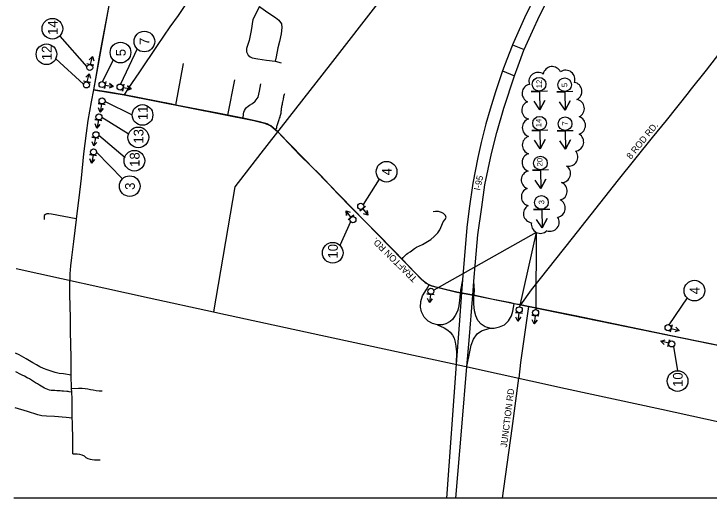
# Model space of a CAD drawing. Extents: x 1123038 to 1172987, y 554419 to 623636.
# Drawn here: x 1123076 to 1134979, y 566570 to 574867 of the extents above; entities that cross this region are included whole.
import ezdxf

# ---------------------------------------------------------------- set-up
doc = ezdxf.new("R2010")
doc.units = 0
for name, color, linetype in [('ANNOTATION', 7, 'Continuous'), ('CENTERLINE', 7, 'Continuous'), ('D_Text_Standard', 7, 'Continuous'), ('Default', 7, 'Continuous'), ('Maine_E911_Roads', 7, 'Continuous'), ('Metwp24L', 7, 'Continuous')]:
    doc.layers.add(name, color=color, linetype=linetype)

msp = doc.modelspace()

# ---------------------------------------------------------------- linework, layer by layer
at = {"layer": 'ANNOTATION'}
msp.add_line((1140976, 566570), (1123076, 566570), dxfattribs=at)
at = {"layer": 'CENTERLINE'}
for points in [[(1125179, 577813), (1125085, 577387), (1125042, 577195), (1124733, 575208), (1124438, 573567)], [(1124438, 573567), (1124965, 573483), (1124965, 573483), (1127185, 573041)], [(1127186, 573041), (1127367, 572996), (1127477, 572951), (1127593, 572849), (1129945, 570430), (1130047, 570325), (1130112, 570269)], [(1130112, 570269), (1130133, 570251), (1130186, 570222), (1130224, 570205), (1130658, 570099), (1130944, 570047), (1136685, 568871)]]:
    msp.add_lwpolyline(points, dxfattribs=at)
at = {"layer": 'D_Text_Standard'}
for p, q in [((1123860, 574488), (1124324, 573959)), ((1125184, 574269), (1124901, 573666)), ((1123794, 574095), (1124267, 573661)), ((1124776, 574080), (1124592, 573708)), ((1124637, 573369), (1125101, 573135)), ((1124582, 573095), (1125031, 572820)), ((1124532, 572789), (1124982, 572404)), ((1124490, 572496), (1124934, 572041)), ((1129331, 572038), (1129054, 571604)), ((1128841, 571307), (1128659, 570900)), ((1132020, 571124), (1130263, 570134)), ((1132020, 571124), (1131730, 569850)), ((1132020, 571124), (1132012, 569802)), ((1134603, 570000), (1134287, 569542)), ((1134369, 569169), (1134439, 568752))]:
    msp.add_line(p, q, dxfattribs=at)
for centre in [(1123735, 574613), (1125309, 574394), (1123633, 574176), (1124901, 574205), (1125278, 573135), (1125206, 572751), (1125138, 572352), (1129456, 572163), (1125059, 571916), (1128534, 570774), (1134728, 570125), (1134439, 568576)]:
    msp.add_circle(centre, 177, dxfattribs=at)
for centre, start, end in [((1132049, 573710), 54.2464, 199.2464), ((1132293, 573809), 24.6964, 169.6964), ((1132525, 573746), 340.1724, 125.1724), ((1131933, 573506), 101.6653, 246.6653), ((1132646, 573540), 295.741, 80.741), ((1132687, 573246), 294.9879, 79.9879), ((1131927, 573217), 110.9351, 255.9351), ((1131936, 572918), 107.5, 252.5), ((1132706, 572956), 287.5, 72.5), ((1132676, 572672), 275.5325, 60.5325), ((1131936, 572620), 107.5, 252.5), ((1131932, 572322), 105.7189, 250.7189), ((1132575, 572413), 256.7337, 41.7337), ((1132451, 572132), 270.7398, 55.7398), ((1131919, 572024), 104.404, 249.404), ((1132394, 571832), 282.7458, 67.7458), ((1131920, 571732), 110.9253, 255.9253), ((1132361, 571540), 279.2887, 64.2887), ((1131956, 571444), 118.2951, 263.2951), ((1132257, 571298), 249.2543, 34.2543), ((1132091, 571263), 170.2227, 315.2227)]:
    msp.add_arc(centre, 156, start, end, dxfattribs=at)
at = {"layer": 'Default'}
for points in [[(1124327, 574016), (1124446, 573988), (1124387, 574002), (1124419, 574138), (1124365, 574079), (1124419, 574138), (1124445, 574065)], [(1124270, 573718), (1124389, 573689), (1124330, 573704), (1124362, 573839), (1124308, 573781), (1124362, 573839), (1124388, 573767)], [(1124650, 573709), (1124629, 573588), (1124639, 573648), (1124777, 573625), (1124715, 573675), (1124777, 573625), (1124706, 573594)], [(1124958, 573666), (1124937, 573546), (1124948, 573606), (1125085, 573582), (1125023, 573633), (1125085, 573582), (1125014, 573552)], [(1132210, 573542), (1131935, 573538), (1132073, 573540), (1132078, 573226), (1132164, 573384), (1132078, 573226), (1131981, 573370)], [(1132648, 573535), (1132373, 573530), (1132510, 573533), (1132515, 573218), (1132601, 573377), (1132515, 573218), (1132419, 573362)], [(1124637, 573311), (1124516, 573333), (1124577, 573322), (1124552, 573185), (1124603, 573247), (1124552, 573185), (1124522, 573256)], [(1124582, 573037), (1124462, 573059), (1124522, 573048), (1124497, 572911), (1124548, 572972), (1124497, 572911), (1124467, 572982)], [(1132217, 572874), (1131942, 572869), (1132080, 572872), (1132085, 572557), (1132171, 572716), (1132085, 572557), (1131988, 572701)], [(1132654, 572866), (1132379, 572862), (1132517, 572864), (1132522, 572550), (1132608, 572708), (1132522, 572550), (1132425, 572694)], [(1124532, 572731), (1124411, 572753), (1124471, 572742), (1124446, 572605), (1124498, 572666), (1124446, 572605), (1124417, 572676)], [(1124490, 572438), (1124370, 572460), (1124430, 572449), (1124405, 572312), (1124456, 572374), (1124405, 572312), (1124375, 572383)], [(1132232, 572193), (1131957, 572188), (1132094, 572191), (1132099, 571876), (1132185, 572035), (1132099, 571876), (1132003, 572020)], [(1128799, 571346), (1128895, 571421), (1128847, 571383), (1128762, 571494), (1128773, 571415), (1128762, 571494), (1128834, 571468)], [(1129096, 571565), (1129000, 571491), (1129048, 571528), (1129133, 571417), (1129122, 571497), (1129133, 571417), (1129061, 571443)], [(1132250, 571518), (1131975, 571513), (1132113, 571516), (1132118, 571201), (1132204, 571360), (1132118, 571201), (1132021, 571345)], [(1130270, 570054), (1130148, 570068), (1130209, 570061), (1130192, 569922), (1130240, 569987), (1130192, 569922), (1130159, 569992)], [(1131783, 569736), (1131662, 569750), (1131723, 569743), (1131706, 569604), (1131753, 569669), (1131706, 569604), (1131672, 569673)], [(1132063, 569689), (1131942, 569704), (1132003, 569696), (1131986, 569558), (1132033, 569622), (1131986, 569558), (1131952, 569627)], [(1134344, 569537), (1134314, 569419), (1134329, 569478), (1134465, 569444), (1134407, 569499), (1134465, 569444), (1134392, 569419)], [(1134273, 569166), (1134303, 569284), (1134288, 569225), (1134152, 569259), (1134210, 569204), (1134152, 569259), (1134225, 569284)]]:
    msp.add_lwpolyline(points, dxfattribs=at)
for centre, radius in [((1124375, 573949), 51.9), ((1132069, 573662), 117), ((1132506, 573654), 117), ((1124318, 573651), 51.9), ((1124586, 573657), 51.9), ((1124894, 573614), 51.9), ((1124585, 573376), 51.9), ((1124531, 573102), 51.9), ((1132076, 572993), 117), ((1132513, 572986), 117), ((1124480, 572796), 51.9), ((1124439, 572503), 51.9), ((1132090, 572312), 117), ((1132109, 571637), 117), ((1129014, 571570), 51.9), ((1128881, 571341), 51.9), ((1130215, 570115), 51.9), ((1131728, 569797), 51.9), ((1132008, 569750), 51.9), ((1134277, 569491), 51.9), ((1134340, 569212), 51.9)]:
    msp.add_circle(centre, radius, dxfattribs=at)
at = {"layer": 'Maine_E911_Roads'}
for points in [[(1134361, 579160), (1133350, 577479), (1133077, 577028), (1132700, 576397), (1132542, 576128), (1132469, 576007), (1132208, 575573), (1132008, 575192), (1131818, 574801), (1131614, 574338)], [(1131810, 574255), (1131981, 574632), (1132046, 574774), (1132130, 574949), (1132308, 575290), (1132437, 575529), (1132637, 575882), (1132759, 576087), (1132857, 576253), (1133391, 577168), (1133611, 577543), (1134066, 578317), (1134254, 578635), (1134576, 579178)], [(1124822, 575809), (1124740, 575234), (1124668, 574827), (1124576, 574348), (1124517, 574035), (1124471, 573763), (1124438, 573567)], [(1126236, 575360), (1126156, 575239), (1126058, 575098), (1125890, 574841), (1125746, 574645), (1125527, 574323), (1125226, 573875), (1125024, 573582), (1124965, 573483)], [(1127283, 574992), (1127165, 574774), (1127137, 574585), (1127102, 574413), (1127059, 574276), (1127060, 574217), (1127087, 574162), (1127122, 574131), (1127157, 574112), (1127255, 574097), (1127398, 574075), (1127550, 574060)], [(1127283, 574992), (1127305, 574978), (1127384, 574919), (1127477, 574858), (1127554, 574807), (1127609, 574762), (1127660, 574698), (1127666, 574633), (1127649, 574526), (1127623, 574392), (1127597, 574287), (1127568, 574134), (1127550, 574060)], [(1135452, 574583), (1135423, 574548), (1135180, 574229), (1134927, 573903), (1134650, 573556), (1134620, 573517), (1134244, 573043), (1134002, 572749), (1133422, 572023), (1132636, 571025), (1131932, 570140), (1131751, 569881)], [(1131614, 574338), (1131607, 574322), (1131515, 574087), (1131444, 573891)], [(1131614, 574338), (1131810, 574255)], [(1131649, 573805), (1131707, 573975), (1131806, 574245), (1131810, 574255)], [(1125851, 573304), (1125978, 574020)], [(1127550, 574060), (1127654, 574030)], [(1131444, 573891), (1131414, 573805), (1131320, 573531), (1131230, 573237), (1131159, 572983), (1131076, 572665), (1131021, 572408), (1130933, 571968), (1130870, 571531), (1130831, 571207), (1130756, 570311)], [(1131444, 573891), (1131649, 573805)], [(1130953, 570288), (1130980, 570617), (1131019, 571083), (1131086, 571557), (1131139, 571936), (1131255, 572474), (1131342, 572835), (1131463, 573254), (1131649, 573805)], [(1126741, 573130), (1126861, 573738)], [(1127000, 573079), (1127009, 573154), (1127015, 573185), (1127026, 573214), (1127041, 573241), (1127061, 573264), (1127085, 573285), (1127111, 573301), (1127161, 573332), (1127204, 573371), (1127241, 573416), (1127258, 573443), (1127279, 573543), (1127304, 573667)], [(1124438, 573567), (1124400, 573358), (1124343, 573039), (1124311, 572822), (1124269, 572468), (1124227, 572052), (1124185, 571715), (1124140, 571358)], [(1124965, 573483), (1124698, 573526), (1124438, 573567)], [(1125851, 573304), (1125778, 573318), (1124965, 573483)], [(1127555, 572883), (1127566, 572896), (1127572, 572903), (1127576, 572916), (1127577, 572929), (1127580, 572943), (1127583, 572957), (1127588, 572972), (1127592, 572987), (1127599, 573005), (1127605, 573023), (1127611, 573042), (1127619, 573060), (1127625, 573080), (1127632, 573098), (1127636, 573116), (1127642, 573134), (1127647, 573150), (1127650, 573167), (1127651, 573185), (1127654, 573201), (1127656, 573218), (1127657, 573234), (1127660, 573251), (1127663, 573267), (1127666, 573284), (1127669, 573303), (1127674, 573323), (1127677, 573343), (1127681, 573363), (1127684, 573383), (1127689, 573404), (1127692, 573424), (1127695, 573442), (1127699, 573458), (1127702, 573475), (1127707, 573491), (1127713, 573504)], [(1126741, 573130), (1126593, 573159), (1125851, 573304)], [(1127000, 573079), (1126993, 573080), (1126741, 573130)], [(1127555, 572883), (1127477, 572951), (1127412, 572981), (1127367, 572996), (1127282, 573018), (1127000, 573079)], [(1127593, 572849), (1127555, 572883)], [(1129721, 570666), (1129601, 570792), (1129260, 571139), (1128862, 571539), (1128614, 571791), (1128330, 572100), (1127974, 572447), (1127593, 572849)], [(1124140, 571358), (1123722, 571438), (1123674, 571444), (1123640, 571442), (1123619, 571432), (1123596, 571410), (1123595, 571382), (1123596, 571344)], [(1129721, 570666), (1129740, 570693), (1129774, 570729), (1129797, 570748), (1129823, 570766), (1129858, 570791), (1129884, 570805), (1129933, 570847), (1129970, 570872), (1130019, 570894), (1130069, 570915), (1130217, 571003), (1130271, 571054), (1130332, 571118), (1130367, 571169), (1130400, 571245), (1130427, 571305), (1130455, 571341), (1130475, 571378), (1130468, 571412), (1130431, 571448), (1130395, 571467), (1130347, 571482), (1130295, 571480), (1130257, 571473)], [(1124140, 571358), (1124139, 571345), (1124094, 570967), (1124060, 570695), (1124044, 570551), (1124035, 570414), (1124032, 570301)], [(1130186, 570222), (1130133, 570251), (1130090, 570287), (1130052, 570319), (1129721, 570666)], [(1124057, 568678), (1124057, 568726), (1124054, 568974), (1124050, 569210), (1124047, 569422), (1124043, 569661), (1124034, 570062), (1124031, 570247), (1124032, 570301)], [(1130756, 570311), (1130723, 570136), (1130710, 570013), (1130702, 569913), (1130687, 569830), (1130670, 569776), (1130633, 569702), (1130587, 569632), (1130545, 569597), (1130473, 569554), (1130413, 569540), (1130326, 569537)], [(1130756, 570311), (1130737, 570087), (1130702, 569537), (1130647, 568863)], [(1130326, 569537), (1130245, 569560), (1130167, 569605), (1130099, 569670), (1130053, 569764), (1130038, 569844), (1130042, 569941), (1130071, 570035), (1130138, 570146), (1130186, 570222)], [(1131642, 569902), (1131582, 569914), (1131283, 569973), (1130944, 570047), (1130658, 570099), (1130486, 570141), (1130308, 570184), (1130224, 570205), (1130186, 570222)], [(1130830, 568823), (1130872, 569271), (1130934, 570045), (1130953, 570288)], [(1131223, 569483), (1131147, 569507), (1131079, 569551), (1131022, 569616), (1130983, 569694), (1130960, 569781), (1130950, 569902), (1130953, 570011), (1130961, 570121), (1130953, 570288)], [(1131223, 569483), (1131300, 569481), (1131390, 569503), (1131473, 569542), (1131547, 569607), (1131595, 569693), (1131617, 569774), (1131642, 569902)], [(1131751, 569881), (1131642, 569902)], [(1131888, 569851), (1131750, 568895), (1131721, 568625)], [(1131888, 569851), (1131751, 569881)], [(1136685, 568871), (1136422, 568922), (1135987, 569019), (1135748, 569065), (1135253, 569164), (1134467, 569320), (1132687, 569692), (1131888, 569851)], [(1130326, 569537), (1130443, 569490), (1130503, 569450), (1130546, 569413), (1130588, 569363), (1130612, 569309), (1130633, 569244), (1130644, 569172), (1130652, 569077), (1130647, 568863)], [(1130830, 568823), (1130883, 569075), (1130906, 569192), (1130944, 569293), (1131009, 569383), (1131084, 569438), (1131223, 569483)], [(1124057, 568678), (1123926, 568697), (1123852, 568708), (1123783, 568725), (1123715, 568743), (1123647, 568767), (1123583, 568792), (1123522, 568820), (1123460, 568852), (1123402, 568887), (1123285, 568957), (1123165, 569023), (1123105, 569054)], [(1130647, 568863), (1130481, 566570)], [(1130644, 566570), (1130743, 567786), (1130830, 568823)], [(1124066, 568388), (1124024, 568394), (1124003, 568395), (1123980, 568396), (1123924, 568402), (1123895, 568405), (1123865, 568406), (1123837, 568409), (1123808, 568410), (1123778, 568413), (1123747, 568414), (1123716, 568417), (1123686, 568421), (1123656, 568429), (1123627, 568440), (1123600, 568456), (1123572, 568472), (1123542, 568489), (1123512, 568508), (1123481, 568527), (1123447, 568547), (1123413, 568569), (1123376, 568590), (1123340, 568612), (1123300, 568633), (1123259, 568657), (1123217, 568679), (1123174, 568701), (1123129, 568725), (1123108, 568736)], [(1124063, 568449), (1124057, 568678)], [(1131441, 566570), (1131609, 567765), (1131721, 568625)], [(1124063, 568449), (1124181, 568452), (1124242, 568452), (1124293, 568448), (1124342, 568444), (1124385, 568434), (1124434, 568424), (1124485, 568415), (1124536, 568411), (1124587, 568410)], [(1124066, 568388), (1124063, 568449)], [(1124075, 567940), (1124072, 568273), (1124066, 568388)], [(1124075, 567940), (1123968, 567951), (1123771, 567971), (1123636, 567975), (1123552, 567979), (1123486, 567996), (1123308, 568052), (1123099, 568117)], [(1124087, 567331), (1124083, 567545), (1124078, 567871), (1124075, 567940)], [(1124087, 567331), (1124161, 567329), (1124200, 567323), (1124240, 567314), (1124276, 567292), (1124308, 567266), (1124344, 567249), (1124382, 567238), (1124417, 567234), (1124453, 567229), (1124489, 567227), (1124527, 567227), (1124550, 567229)]]:
    msp.add_lwpolyline(points, dxfattribs=at)
at = {"layer": 'Metwp24L'}
for points in [[(1132505, 579176), (1132202, 578786), (1131172, 577456), (1130264, 576283), (1129347, 575104), (1128489, 574000), (1127306, 572480), (1126860, 571905)], [(1126860, 571905), (1126495, 569760)], [(1123115, 570503), (1125390, 570002)], [(1125390, 570002), (1126495, 569760)], [(1126495, 569760), (1126565, 569745), (1128542, 569315), (1130793, 568831), (1132522, 568448), (1134165, 568093), (1135956, 567702), (1137599, 567347), (1137816, 567290)]]:
    msp.add_lwpolyline(points, dxfattribs=at)

# ---------------------------------------------------------------- texts
at = {"layer": 'D_Text_Standard'}
for s, height, rotation, p in [('14', 167.1, 90, (1123824, 574507)), ('7', 167, 90, (1125397, 574334)), ('12', 167.1, 90, (1123721, 574074)), ('5', 167, 90, (1124990, 574142)), ('12', 94, 90.4263, (1132116, 573595)), ('5', 94, 90.4263, (1132551, 573613)), ('11', 167.1, 90, (1125366, 573047)), ('14', 94, 90.4263, (1132108, 572928)), ('7', 94, 90.4263, (1132560, 572954)), ('8 ROD RD.', 112, 50.9852, (1133640, 572368)), ('13', 167.1, 90, (1125294, 572645)), ('18', 167.1, 90, (1125227, 572247)), ('20', 94, 90.4263, (1132126, 572256)), ('4', 167, 90, (1129544, 572100)), ('I-95', 112, 77.6428, (1131059, 571833)), ('3', 167, 90, (1125147, 571853)), ('3', 94, 90.4263, (1132156, 571605)), ('TRAFTON RD. ', 111.99, 135.4782, (1129990, 570339)), ('10', 167.1, 90, (1128622, 570675)), ('4', 167, 90, (1134816, 570062)), ('10', 167.1, 90, (1134527, 568476)), ('JUNCTION RD', 111.99, 82.763, (1131517, 567434))]:
    msp.add_text(s, height=height, rotation=rotation, dxfattribs=at).set_placement(p)

doc.saveas('drawing.dxf')
